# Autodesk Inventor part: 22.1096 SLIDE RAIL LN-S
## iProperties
Created: 2007-06
Part Number: 22.1096 SLIDE RAIL LN-S
Material: Brass, Soft Yellow
Document SubType Name: Modeling
Designer: Andy Moles
Density: 8.47 g/cm^3
Mass: 0.455206 g
Surface Area: 2.56671 cm^2
Volume: 0.0537433 cm^3
Author: Andy Moles
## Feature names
1. Extrusion1
2. Extrusion2
3. Circular Pattern1
4. Extrusion3
